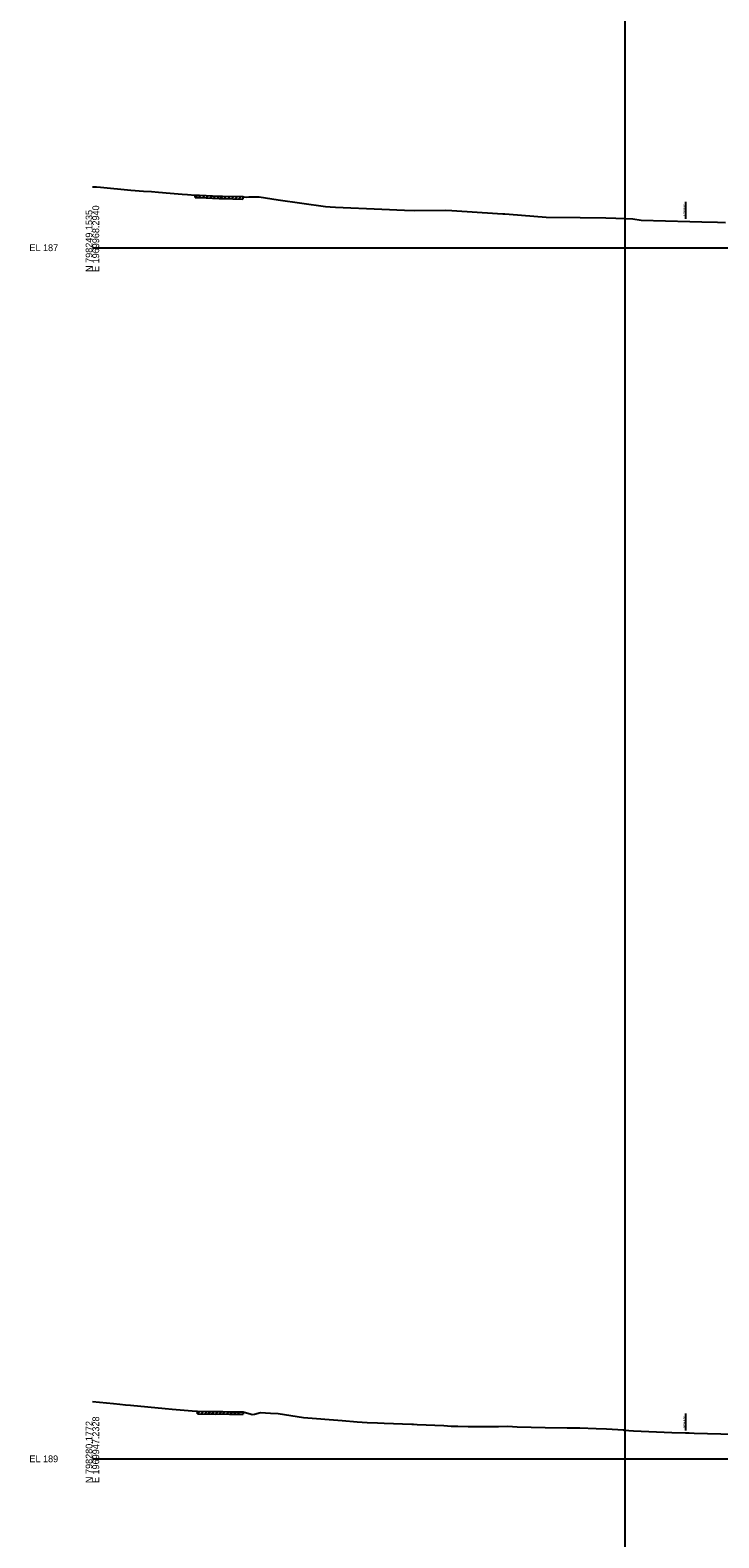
# Model space of a CAD drawing. Extents: x -26 to 1986619, y -10 to 827846.
# Drawn here: x -26 to 259, y 12967 to 13590 of the extents above; entities that cross this region are included whole.
import ezdxf

# ---------------------------------------------------------------- set-up
doc = ezdxf.new("R2010")
doc.units = 0
for name, color, linetype in [('Default', 7, 'Continuous'), ('RD_EX_Bridge', 7, 'Continuous'), ('RD_GPK_XS_Cell', 7, 'Continuous'), ('RD_Sketch7', 7, 'Continuous'), ('RD_XS_ExGround', 7, 'Continuous'), ('RD_XS_ExPaveRet', 7, 'Continuous')]:
    doc.layers.add(name, color=color, linetype=linetype)

msp = doc.modelspace()

# ---------------------------------------------------------------- linework, layer by layer
at = {"layer": 'RD_EX_Bridge'}
for p, q in [((245, 13511.91), (245, 13518.91)), ((245, 13011.71), (245, 13018.71))]:
    msp.add_line(p, q, dxfattribs=at)
at = {"layer": 'RD_GPK_XS_Cell'}
for p, q in [((0, 13500), (300, 13500)), ((0, 13000), (300, 13000))]:
    msp.add_line(p, q, dxfattribs=at)
at = {"layer": 'RD_Sketch7'}
msp.add_line((220, 0), (220, 21279.28), dxfattribs=at)
at = {"layer": 'RD_XS_ExGround'}
for points in [[(0, 13525.12), (1.76, 13525.12), (3.39, 13524.97), (15.83, 13523.79), (21.09, 13523.39), (24.44, 13523.16), (27.25, 13522.95), (32.11, 13522.46), (33.69, 13522.45), (37.06, 13522.17), (39.28, 13521.93), (42.44, 13521.72), (44.21, 13521.69), (52.28, 13521.33), (53.72, 13521.3), (62.06, 13521.1), (62.52, 13521.01), (63.64, 13520.83), (64.67, 13521.02), (68.78, 13521.08), (76.71, 13519.76), (96.18, 13517.02), (98.13, 13516.82), (100.4, 13516.74), (119.47, 13515.97), (128.9, 13515.47), (132.8, 13515.35), (145.64, 13515.51), (148.45, 13515.41), (167.29, 13514.18), (169.42, 13514), (170.3, 13513.96), (172.1, 13513.83), (187.32, 13512.68), (201.31, 13512.5), (211.94, 13512.35), (216.14, 13512.21), (223.14, 13511.9), (226.54, 13511.43), (246.67, 13510.86), (251.62, 13510.75), (258.03, 13510.5), (261.38, 13510.47)], [(0, 13023.64), (8.76, 13022.78), (11.37, 13022.53), (13.71, 13022.31), (15.79, 13022.11), (30.03, 13020.73), (32.91, 13020.54), (42.89, 13019.67), (43.36, 13019.63), (50.73, 13019.49), (53.87, 13019.52), (56.54, 13019.42), (62.26, 13019.38), (65.57, 13018.46), (66.01, 13018.36), (66.97, 13018.5), (69.39, 13019.07), (73.55, 13018.82), (76.66, 13018.68), (87.14, 13017.01), (103.16, 13015.82), (109.32, 13015.33), (113.42, 13015.04), (117.75, 13014.82), (120.42, 13014.66), (131.92, 13014.3), (132.5, 13014.27), (134.04, 13014.18), (145.03, 13013.76), (148.09, 13013.54), (150.85, 13013.44), (155.09, 13013.35), (167.59, 13013.41), (171.54, 13013.42), (175.42, 13013.15), (186.88, 13012.93), (196.01, 13012.85), (201.16, 13012.85), (207.92, 13012.57), (212.22, 13012.34), (219.25, 13011.92), (219.56, 13011.89), (223.44, 13011.53), (239.15, 13010.83), (244.91, 13010.71), (246.41, 13010.67), (248.4, 13010.61), (264.96, 13010.23)]]:
    msp.add_lwpolyline(points, dxfattribs=at)
at = {"layer": 'RD_XS_ExPaveRet'}
for p, q in [((42.44, 13520.72), (42.44, 13521.72)), ((42.44, 13520.72), (43.42, 13521.7)), ((42.44, 13520.72), (44.21, 13520.69)), ((43.94, 13520.69), (44.9, 13521.66)), ((44.21, 13520.69), (52.28, 13520.33)), ((45.44, 13520.63), (46.4, 13521.59)), ((46.94, 13520.56), (47.9, 13521.52)), ((48.44, 13520.5), (49.4, 13521.45)), ((49.94, 13520.43), (50.9, 13521.39)), ((51.44, 13520.36), (52.4, 13521.32)), ((52.28, 13520.33), (53.72, 13520.3)), ((52.94, 13520.31), (53.92, 13521.3)), ((53.72, 13520.3), (62.06, 13520.1)), ((54.44, 13520.29), (55.42, 13521.26)), ((55.94, 13520.25), (56.92, 13521.23)), ((57.44, 13520.21), (58.42, 13521.19)), ((58.94, 13520.18), (59.92, 13521.16)), ((60.44, 13520.14), (61.42, 13521.12)), ((62.06, 13521.1), (62.06, 13520.1)), ((43.36, 13018.63), (43.36, 13019.63)), ((43.36, 13018.63), (44.34, 13019.61)), ((43.36, 13018.63), (50.73, 13018.49)), ((44.86, 13018.6), (45.84, 13019.58)), ((46.36, 13018.57), (47.34, 13019.56)), ((47.86, 13018.55), (48.84, 13019.53)), ((49.36, 13018.52), (50.34, 13019.5)), ((50.73, 13018.49), (53.87, 13018.52)), ((50.86, 13018.49), (51.86, 13019.5)), ((52.36, 13018.51), (53.36, 13019.52)), ((53.86, 13018.52), (54.82, 13019.49)), ((53.87, 13018.52), (56.54, 13018.42)), ((55.36, 13018.47), (56.32, 13019.43)), ((56.54, 13018.42), (62.26, 13018.38)), ((56.86, 13018.42), (57.85, 13019.41)), ((58.36, 13018.41), (59.35, 13019.4)), ((59.86, 13018.4), (60.85, 13019.39)), ((62.26, 13019.38), (62.26, 13018.38))]:
    msp.add_line(p, q, dxfattribs=at)

# ---------------------------------------------------------------- texts
at = {"layer": 'Default'}
for p in [(0, 13500), (0, 13000)]:
    msp.add_text('-', height=0.0001, dxfattribs=at).set_placement(p)
at = {"layer": 'RD_EX_Bridge'}
for p in [(244.75, 13513.05), (244.75, 13012.85)]:
    msp.add_text('NEW R/W ', height=0.75, rotation=90, dxfattribs=at).set_placement(p)
at = {"layer": 'RD_GPK_XS_Cell'}
for s, p in [('N 798249.1535', (0, 13490)), ('E 1969968.2940', (2.8, 13490)), ('N 798280.1772', (0, 12990)), ('E 1969947.2328', (2.8, 12990))]:
    msp.add_text(s, height=2.8, rotation=90, dxfattribs=at).set_placement(p)
for s, p in [('EL 187', (-26, 13498.6)), ('EL 189', (-26, 12998.6))]:
    msp.add_text(s, height=2.8, dxfattribs=at).set_placement(p)

doc.saveas('drawing.dxf')
